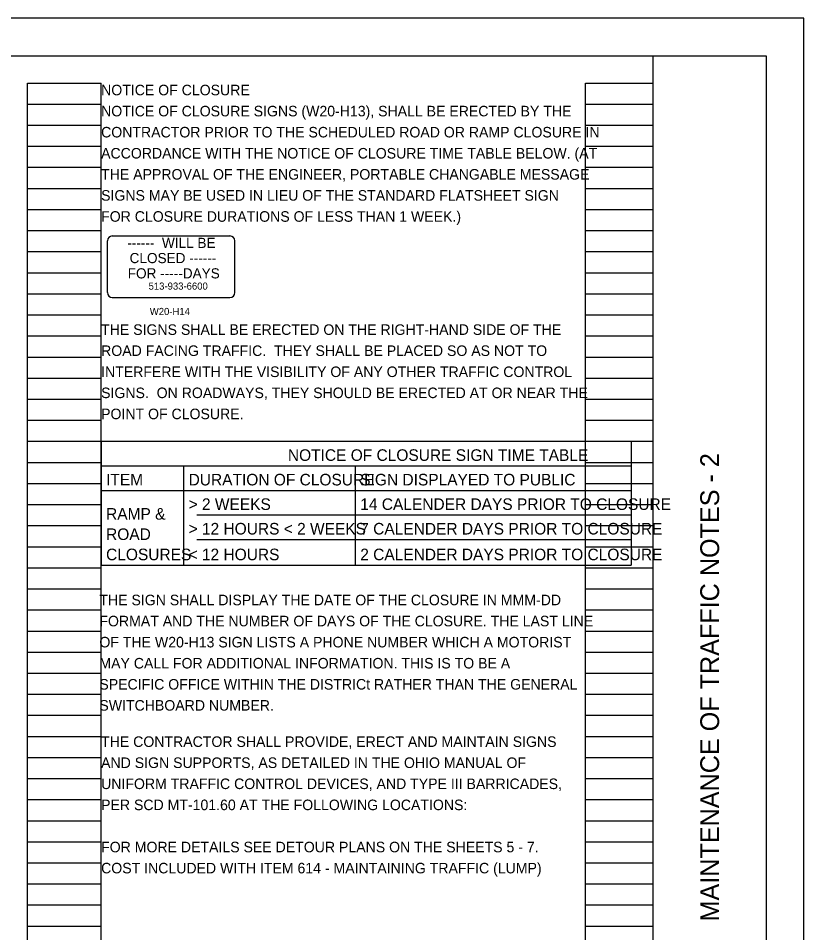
# Model space of a CAD drawing. Extents: x -98 to 46, y -2 to 66.
# Drawn here: x 23.56 to 34, y 9.85 to 22 of the extents above; entities that cross this region are included whole.
import ezdxf

# ---------------------------------------------------------------- set-up
doc = ezdxf.new("R2010")
doc.units = 0
for name, color, linetype in [('Default', 7, 'Continuous'), ('SC_Scratch1', 7, 'Continuous'), ('SH_Border', 7, 'Continuous'), ('SH_Cut_Line', 7, 'Continuous'), ('SH_Data', 7, 'Continuous')]:
    doc.layers.add(name, color=color, linetype=linetype)

msp = doc.modelspace()

# ---------------------------------------------------------------- linework, layer by layer
at = {"layer": 'Default'}
for p, q in [((24.808, 19.108), (26.373, 19.108)), ((24.743, 18.356), (24.743, 19.043)), ((26.438, 18.356), (26.438, 19.043)), ((24.808, 18.291), (26.373, 18.291))]:
    msp.add_line(p, q, dxfattribs=at)
for centre, start, end in [((24.808, 19.043), 90, 180), ((26.373, 19.043), 0, 90), ((24.808, 18.356), 180, 270), ((26.373, 18.356), 270, 0)]:
    msp.add_arc(centre, 0.0649, start, end, dxfattribs=at)
at = {"layer": 'SH_Border'}
msp.add_line((32, 0.5), (32, 21.5), dxfattribs=at)
msp.add_lwpolyline([(1.5, 21.5), (33.5, 21.5), (33.5, 0.5), (1.5, 0.5)], close=True, dxfattribs=at)
at = {"layer": 'SH_Cut_Line'}
msp.add_lwpolyline([(0, 0), (34, 0), (34, 22), (0, 22)], close=True, dxfattribs=at)
at = {"layer": 'SH_Data'}
for p, q in [((23.68, 0.98), (23.68, 21.14)), ((23.68, 21.14), (24.66, 21.14)), ((24.66, 0.98), (24.66, 21.14)), ((31.1, 0.98), (31.1, 21.14)), ((31.1, 21.14), (32, 21.14)), ((32, 0.98), (32, 21.14)), ((23.68, 20.86), (24.66, 20.86)), ((31.1, 20.86), (32, 20.86)), ((23.68, 20.58), (24.66, 20.58)), ((31.1, 20.58), (32, 20.58)), ((23.68, 20.3), (24.66, 20.3)), ((31.1, 20.3), (32, 20.3)), ((23.68, 20.02), (24.66, 20.02)), ((31.1, 20.02), (32, 20.02)), ((23.68, 19.74), (24.66, 19.74)), ((31.1, 19.74), (32, 19.74)), ((23.68, 19.46), (24.66, 19.46)), ((31.1, 19.46), (32, 19.46)), ((23.68, 19.18), (24.66, 19.18)), ((31.1, 19.18), (32, 19.18)), ((23.68, 18.9), (24.66, 18.9)), ((31.1, 18.9), (32, 18.9)), ((23.68, 18.62), (24.66, 18.62)), ((31.1, 18.62), (32, 18.62)), ((23.68, 18.34), (24.66, 18.34)), ((31.1, 18.34), (32, 18.34)), ((23.68, 18.06), (24.66, 18.06)), ((31.1, 18.06), (32, 18.06)), ((23.68, 17.78), (24.66, 17.78)), ((31.1, 17.78), (32, 17.78)), ((23.68, 17.5), (24.66, 17.5)), ((31.1, 17.5), (32, 17.5)), ((23.68, 17.22), (24.66, 17.22)), ((31.1, 17.22), (32, 17.22)), ((23.68, 16.94), (24.66, 16.94)), ((31.1, 16.94), (32, 16.94)), ((23.68, 16.66), (24.66, 16.66)), ((31.1, 16.66), (32, 16.66)), ((23.68, 16.38), (24.66, 16.38)), ((24.66, 16.38), (31.706, 16.38)), ((24.66, 16.38), (24.66, 15.402)), ((31.1, 16.38), (32, 16.38)), ((31.706, 16.38), (31.706, 14.734)), ((23.68, 16.1), (24.66, 16.1)), ((24.66, 16.054), (31.706, 16.054)), ((25.757, 16.054), (25.757, 15.402)), ((28.039, 16.054), (28.039, 15.402)), ((31.1, 16.1), (32, 16.1)), ((23.68, 15.82), (24.66, 15.82)), ((31.1, 15.82), (32, 15.82)), ((24.66, 15.728), (31.706, 15.728)), ((23.68, 15.54), (24.66, 15.54)), ((31.1, 15.54), (32, 15.54)), ((24.66, 15.402), (24.66, 15.076)), ((25.757, 15.402), (25.757, 15.076)), ((25.931, 15.402), (31.706, 15.402)), ((28.039, 15.402), (28.039, 15.076)), ((23.68, 15.26), (24.66, 15.26)), ((31.1, 15.26), (32, 15.26)), ((24.66, 15.076), (24.66, 14.734)), ((25.757, 15.076), (25.757, 14.734)), ((25.931, 15.076), (31.706, 15.076)), ((28.039, 15.076), (28.039, 14.734)), ((23.68, 14.98), (24.66, 14.98)), ((31.1, 14.98), (32, 14.98)), ((23.68, 14.7), (24.66, 14.7)), ((24.66, 14.734), (31.706, 14.734)), ((31.1, 14.7), (32, 14.7)), ((23.68, 14.42), (24.66, 14.42)), ((31.1, 14.42), (32, 14.42)), ((23.68, 14.14), (24.66, 14.14)), ((31.1, 14.14), (32, 14.14)), ((23.68, 13.86), (24.66, 13.86)), ((31.1, 13.86), (32, 13.86)), ((23.68, 13.58), (24.66, 13.58)), ((31.1, 13.58), (32, 13.58)), ((23.68, 13.3), (24.66, 13.3)), ((31.1, 13.3), (32, 13.3)), ((23.68, 13.02), (24.66, 13.02)), ((31.1, 13.02), (32, 13.02)), ((23.68, 12.74), (24.66, 12.74)), ((31.1, 12.74), (32, 12.74)), ((23.68, 12.46), (24.66, 12.46)), ((31.1, 12.46), (32, 12.46)), ((23.68, 12.18), (24.66, 12.18)), ((31.1, 12.18), (32, 12.18)), ((23.68, 11.9), (24.66, 11.9)), ((31.1, 11.9), (32, 11.9)), ((23.68, 11.62), (24.66, 11.62)), ((31.1, 11.62), (32, 11.62)), ((23.68, 11.34), (24.66, 11.34)), ((31.1, 11.34), (32, 11.34)), ((23.68, 11.06), (24.66, 11.06)), ((31.1, 11.06), (32, 11.06)), ((23.68, 10.78), (24.66, 10.78)), ((31.1, 10.78), (32, 10.78)), ((23.68, 10.5), (24.66, 10.5)), ((31.1, 10.5), (32, 10.5)), ((23.68, 10.22), (24.66, 10.22)), ((31.1, 10.22), (32, 10.22)), ((23.68, 9.94), (24.66, 9.94)), ((31.1, 9.94), (32, 9.94))]:
    msp.add_line(p, q, dxfattribs=at)

# ---------------------------------------------------------------- texts
at = {"layer": 'SC_Scratch1'}
for s, height, p in [('NOTICE OF CLOSURE', 0.14, (24.66, 20.977)), ('NOTICE OF CLOSURE SIGNS (W20-H13), SHALL BE ERECTED BY THE ', 0.14, (24.66, 20.697)), ('CONTRACTOR PRIOR TO THE SCHEDULED ROAD OR RAMP CLOSURE IN ', 0.14, (24.66, 20.417)), ('ACCORDANCE WITH THE NOTICE OF CLOSURE TIME TABLE BELOW. (AT ', 0.14, (24.66, 20.137)), ('THE APPROVAL OF THE ENGINEER, PORTABLE CHANGABLE MESSAGE ', 0.14, (24.66, 19.857)), ('SIGNS MAY BE USED IN LIEU OF THE STANDARD FLATSHEET SIGN ', 0.14, (24.66, 19.577)), ('FOR CLOSURE DURATIONS OF LESS THAN 1 WEEK.)', 0.14, (24.66, 19.297)), ('------  WILL BE', 0.135, (25.008, 18.949)), ('CLOSED ------', 0.135, (25.039, 18.747)), ('FOR -----DAYS', 0.135, (25.014, 18.544)), ('513-933-6600', 0.0945, (25.291, 18.395)), ('W20-H14', 0.0945, (25.307, 18.058)), ('THE SIGNS SHALL BE ERECTED ON THE RIGHT-HAND SIDE OF THE ', 0.14, (24.66, 17.794)), ('ROAD FACING TRAFFIC.  THEY SHALL BE PLACED SO AS NOT TO ', 0.14, (24.66, 17.514)), ('INTERFERE WITH THE VISIBILITY OF ANY OTHER TRAFFIC CONTROL ', 0.14, (24.66, 17.234)), ('SIGNS.  ON ROADWAYS, THEY SHOULD BE ERECTED AT OR NEAR THE ', 0.14, (24.66, 16.954)), ('POINT OF CLOSURE. ', 0.14, (24.66, 16.674)), ('NOTICE OF CLOSURE SIGN TIME TABLE', 0.154, (27.143, 16.12)), ('ITEM', 0.154, (24.726, 15.794)), ('DURATION OF CLOSURE', 0.154, (25.823, 15.794)), ('SIGN DISPLAYED TO PUBLIC', 0.154, (28.105, 15.794)), ('> 2 WEEKS', 0.154, (25.823, 15.468)), ('14 CALENDER DAYS PRIOR TO CLOSURE', 0.154, (28.105, 15.468)), ('RAMP & ', 0.154, (24.726, 15.339)), ('ROAD ', 0.154, (24.726, 15.069)), ('> 12 HOURS < 2 WEEKS', 0.154, (25.823, 15.142)), ('7 CALENDER DAYS PRIOR TO CLOSURE', 0.154, (28.105, 15.142)), ('CLOSURES', 0.154, (24.726, 14.8)), ('< 12 HOURS', 0.154, (25.823, 14.8)), ('2 CALENDER DAYS PRIOR TO CLOSURE', 0.154, (28.105, 14.8)), ('THE SIGN SHALL DISPLAY THE DATE OF THE CLOSURE IN MMM-DD ', 0.14, (24.637, 14.202)), ('FORMAT AND THE NUMBER OF DAYS OF THE CLOSURE. THE LAST LINE ', 0.14, (24.637, 13.922)), ('OF THE W20-H13 SIGN LISTS A PHONE NUMBER WHICH A MOTORIST ', 0.14, (24.637, 13.642)), ('MAY CALL FOR ADDITIONAL INFORMATION. THIS IS TO BE A ', 0.14, (24.637, 13.362)), ('SPECIFIC OFFICE WITHIN THE DISTRICt RATHER THAN THE GENERAL ', 0.14, (24.637, 13.082)), ('SWITCHBOARD NUMBER.', 0.14, (24.637, 12.802)), ('THE CONTRACTOR SHALL PROVIDE, ERECT AND MAINTAIN SIGNS ', 0.14, (24.66, 12.32)), ('AND SIGN SUPPORTS, AS DETAILED IN THE OHIO MANUAL OF ', 0.14, (24.66, 12.04)), ('UNIFORM TRAFFIC CONTROL DEVICES, AND TYPE III BARRICADES, ', 0.14, (24.66, 11.76)), ('PER SCD MT-101.60 AT THE FOLLOWING LOCATIONS:', 0.14, (24.66, 11.48)), ('FOR MORE DETAILS SEE DETOUR PLANS ON THE SHEETS 5 - 7.', 0.14, (24.66, 10.92)), ('COST INCLUDED WITH ITEM 614 - MAINTAINING TRAFFIC (LUMP)', 0.14, (24.66, 10.64))]:
    msp.add_text(s, height=height, dxfattribs=at).set_placement(p)
at = {"layer": 'SH_Data'}
msp.add_text('MAINTENANCE OF TRAFFIC NOTES - 2', height=0.25, rotation=90, dxfattribs=at).set_placement((32.875, 10.001))

doc.saveas('drawing.dxf')
